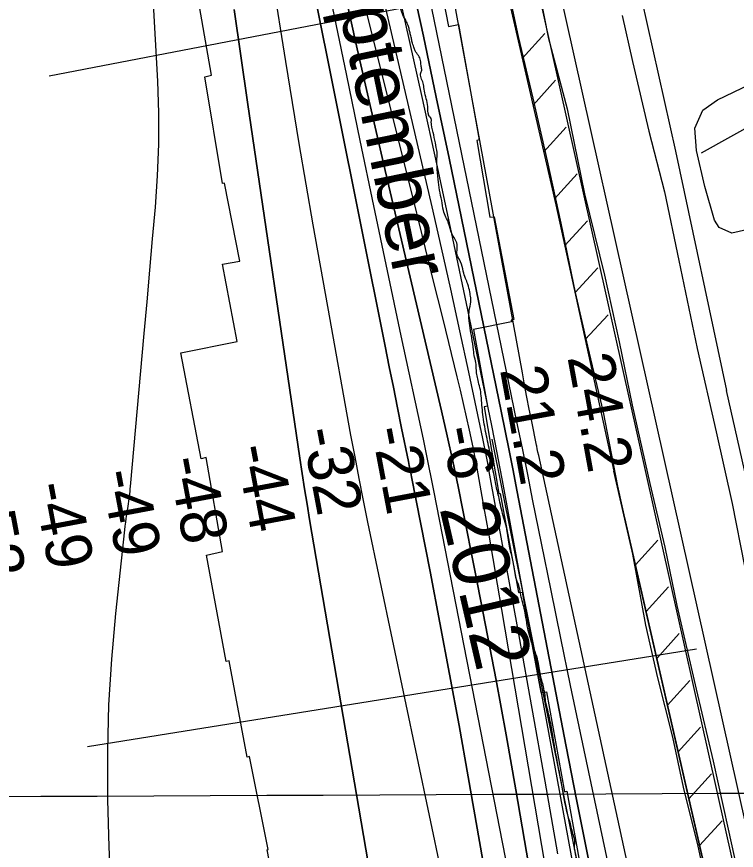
# Model space of a CAD drawing. Extents: x 3419139 to 3457078, y 540382 to 565875.
# Drawn here: x 3439284 to 3440334, y 551821 to 553037 of the extents above; entities that cross this region are included whole.
import ezdxf

# ---------------------------------------------------------------- set-up
doc = ezdxf.new("R2010")
doc.units = 0
for name, color, linetype in [('V-FLOD-BASE', 7, 'Continuous'), ('V-GRID-MAJR', 7, 'Continuous'), ('V-LEVE-TOET', 7, 'Continuous'), ('V-RIVR-EDGE', 7, 'Continuous'), ('V-RIVR-IDEN', 7, 'Continuous'), ('V-RIVR-RANG', 7, 'Continuous'), ('V-ROAD-CNTR', 7, 'Continuous'), ('V-RRAP-FSHR', 7, 'Continuous'), ('V-RRAP-RVMT', 7, 'Continuous'), ('V-SITE-VEGE', 7, 'Continuous'), ('V-SURV-LINE', 7, 'Continuous'), ('V-TOPO-DPTH', 7, 'Continuous'), ('V-TOPO-MAJR', 7, 'Continuous'), ('V-TOPO-MINR', 7, 'Continuous'), ('V-TOPO-SHOR', 7, 'Continuous'), ('V-TOPO-WATR', 7, 'Continuous')]:
    doc.layers.add(name, color=color, linetype=linetype)

msp = doc.modelspace()

# ---------------------------------------------------------------- linework, layer by layer
at = {"layer": 'V-FLOD-BASE'}
msp.add_lwpolyline([(3440043.2, 553091.6), (3440059.9, 553007.1), (3440087.4, 552902.3), (3440113, 552778.5), (3440141.9, 552659.9), (3440163.5, 552562.5), (3440182.4, 552470.3), (3440208, 552356), (3440229.9, 552263.3), (3440247.7, 552177.9), (3440275.5, 552056), (3440300.5, 551951), (3440322.5, 551851.8), (3440341.1, 551767.6), (3440361.6, 551677.7), (3440384.4, 551584.4), (3440400, 551514.2), (3440412.8, 551457.5), (3440426.1, 551391.2), (3440438.9, 551339), (3440453.6, 551276.9), (3440457.5, 551259.7)], dxfattribs=at)
at = {"layer": 'V-GRID-MAJR'}
msp.add_spline([(3423248.5, 551833.1), (3428523.1, 551854.2), (3433797.7, 551876), (3439072.3, 551898.7), (3444346.9, 551922.1), (3449621.5, 551946.2), (3454896.1, 551971.2)], degree=3, dxfattribs=at)
at = {"layer": 'V-LEVE-TOET'}
for points in [[(3440395.7, 551317.5), (3440385.5, 551375.7), (3440369.1, 551439.4), (3440351.4, 551520.9), (3440332.3, 551605.9), (3440306.4, 551696.4), (3440293.7, 551756.9), (3440278.7, 551827), (3440257.1, 551913.1), (3440241.8, 551985.9), (3440219.9, 552072.6), (3440202.4, 552149.6), (3440183.1, 552253.1), (3440161.2, 552352.3), (3440140.4, 552460.2), (3440117.7, 552556.3), (3440099.9, 552634.8), (3440078.9, 552735.7), (3440058.9, 552826.8), (3440037.8, 552918.2), (3440016.5, 553008.1), (3439996.8, 553101.5)], [(3440167.9, 553038.6), (3440182.9, 552971.3), (3440206.5, 552869.9), (3440229.5, 552781.3), (3440250.6, 552681), (3440277.4, 552552.9), (3440304.9, 552431.2), (3440328.2, 552326.7), (3440346.4, 552235.3), (3440367.8, 552133.6), (3440389.9, 552031), (3440415.2, 551920.6), (3440438.8, 551818.5), (3440464.3, 551705.3), (3440484.8, 551610.8), (3440506.1, 551517.8), (3440527.5, 551415.2), (3440545.7, 551326.4), (3440564.3, 551242.3), (3440575.7, 551189.9), (3440580.9, 551161.3)]]:
    msp.add_lwpolyline(points, dxfattribs=at)
at = {"layer": 'V-RIVR-EDGE'}
for points in [[(3439898, 552838.8), (3439895.2, 552852.9), (3439892, 552868.1), (3439889.3, 552883.9), (3439888.9, 552888.5), (3439886.8, 552891), (3439885.4, 552893.5), (3439884.7, 552896.3), (3439883.7, 552909), (3439881.2, 552919.9), (3439878.8, 552931.2), (3439877.4, 552940), (3439873.9, 552955.1), (3439875, 552957.6), (3439875, 552962.5), (3439874, 552969.2), (3439873.6, 552972.8), (3439870.5, 552980.2), (3439865.9, 552986.9), (3439863.8, 552992.5), (3439861.4, 552999.9), (3439860.3, 553005.6), (3439858.6, 553011.9), (3439857.2, 553017.9), (3439855.4, 553023.9), (3439852.3, 553031.3), (3439848.8, 553037.3), (3439845.6, 553045.1), (3439842.1, 553056.7), (3439838.3, 553071.2), (3439833.8, 553092.3), (3439828.9, 553114.2), (3439822.9, 553128.3), (3439821.9, 553133.9), (3439821.9, 553141.3), (3439820.5, 553150.5), (3439817, 553162.1), (3439816, 553169.9), (3439815.3, 553181.9), (3439812.9, 553202.3), (3439811.8, 553208.3), (3439810.4, 553213.6), (3439806.6, 553223.1), (3439803.4, 553233), (3439801, 553245.7), (3439798.2, 553251.3), (3439796.5, 553255.2), (3439794.4, 553261.6), (3439791.9, 553279.2), (3439786.7, 553298.2), (3439783.9, 553315.1), (3439782.9, 553320.1), (3439780.1, 553330), (3439779, 553338.4), (3439778, 553346.2), (3439774.5, 553358.9), (3439769.6, 553372.3), (3439764, 553387.8), (3439758.1, 553404.4), (3439752.8, 553419.5), (3439741.6, 553446.3), (3439736.7, 553454.1), (3439731.4, 553464.7), (3439730.4, 553470), (3439729.7, 553476.7), (3439729.7, 553486.5), (3439729, 553489), (3439726.9, 553492.2), (3439726.2, 553498.9), (3439724.9, 553513.7), (3439721.4, 553531.3), (3439717.5, 553552.8), (3439712.3, 553570.4), (3439710.2, 553579.6), (3439708.5, 553593.7), (3439705, 553614.2), (3439704.7, 553622.3), (3439704.7, 553626.5), (3439708.6, 553631.1), (3439711.1, 553635.3), (3439710.7, 553638.8), (3439709.3, 553643.7), (3439705.8, 553645.9), (3439697.7, 553653.6), (3439695.6, 553658.9), (3439695.3, 553664.9), (3439694.6, 553680.4), (3439696.7, 553685), (3439699.6, 553689.2), (3439699.2, 553692.8), (3439697.1, 553699.8), (3439696.1, 553710), (3439696.1, 553716.4), (3439695.4, 553735.8), (3439695.8, 553748.8), (3439695.2, 553762.5), (3439697.6, 553766.8), (3439697.7, 553771.3), (3439697, 553779.1), (3439694.9, 553788.3), (3439690.3, 553807.6), (3439684.4, 553823.5), (3439683.4, 553830.6), (3439684.8, 553836.2), (3439684.1, 553840.8), (3439681.6, 553846.8), (3439678.8, 553854.9), (3439676, 553862.3), (3439673.9, 553876.4), (3439675.4, 553881), (3439676.4, 553885.6), (3439676.5, 553890.8), (3439674, 553896.8), (3439671.5, 553900), (3439667.7, 553908.1), (3439664.2, 553925.8), (3439659.7, 553946.2), (3439656.9, 553950.1), (3439654.8, 553956.4), (3439651.7, 553979.7), (3439648.5, 553996.3), (3439644.7, 554015.7), (3439637.4, 554038.9), (3439632.8, 554059), (3439619.2, 554107.3), (3439614.7, 554128.1), (3439609.1, 554159.9), (3439602.5, 554201.1), (3439596.6, 554223.3), (3439592.8, 554245.2), (3439591, 554261.8), (3439592.8, 554281.8), (3439596.1, 554295.2), (3439598.2, 554308.6), (3439596.5, 554318.1), (3439590.5, 554329.4), (3439580.3, 554345.6), (3439576.5, 554348.5), (3439571.9, 554348.8), (3439568.4, 554349.6), (3439562.4, 554351.3), (3439561.3, 554354.9), (3439561, 554358), (3439561, 554363.3), (3439562.8, 554369.6), (3439563.8, 554378.5), (3439561.1, 554391.1), (3439558.3, 554406), (3439553.4, 554429.6), (3439551.7, 554441.9), (3439549.2, 554448.6), (3439546.8, 554453.6), (3439544.7, 554460.6), (3439544, 554469.8), (3439544, 554477.9), (3439543.9, 554480)], [(3440024.9, 552173.6), (3440019.4, 552196.1), (3440016.9, 552207.4), (3440012.7, 552218.7), (3440010.6, 552231), (3440007.8, 552246.2), (3440003.3, 552264.5), (3439999.5, 552289.2), (3439992.5, 552315.3), (3439989.4, 552329), (3439984.5, 552349.8), (3439980.3, 552370.6), (3439975.8, 552397.1), (3439969.9, 552424.9), (3439965, 552453.1), (3439962.3, 552480.6), (3439960.9, 552492.6), (3439958.1, 552503.9), (3439956, 552513.1), (3439955, 552521.5), (3439954.6, 552529.6), (3439952.5, 552540.2), (3439950.8, 552550.8), (3439948.4, 552568.4), (3439944.2, 552597), (3439944.6, 552607.9), (3439946.8, 552620.9), (3439946.8, 552626.9), (3439945.4, 552635.4), (3439942.6, 552646.7), (3439939.1, 552655.1), (3439935.9, 552665.7), (3439932.1, 552679.1), (3439927.2, 552689), (3439926.9, 552704.8), (3439919.2, 552720.4), (3439914.6, 552735.2), (3439906.9, 552754.2), (3439904.5, 552768.7), (3439901.3, 552783.8), (3439899.3, 552799.7), (3439897.6, 552818.7), (3439898, 552838.8)], [(3440142.2, 551559.1), (3440138.4, 551591.5), (3440135.6, 551613.4), (3440133.2, 551626.8), (3440131.4, 551638.4), (3440130.8, 551646.1), (3440130.1, 551651.4), (3440129, 551656), (3440126.9, 551665.2), (3440126.2, 551672.9), (3440124.5, 551681), (3440127, 551684.6), (3440127, 551686.7), (3440127, 551691.3), (3440125.6, 551700.8), (3440126, 551707.1), (3440125.6, 551711), (3440123.9, 551714.5), (3440120.4, 551717), (3440120.4, 551718.8), (3440119, 551728.3), (3440113.8, 551755.8), (3440107.1, 551779.4), (3440101.9, 551803.4), (3440099.1, 551819.6), (3440098.1, 551825.9), (3440098.8, 551835.1), (3440097.4, 551840.4), (3440092.2, 551859.4), (3440088, 551874.2), (3440079.3, 551918.7), (3440073, 551951.4), (3440067.1, 551985.6), (3440062.9, 552008.9), (3440057.7, 552031.1), (3440056, 552039.2), (3440055.6, 552043.8), (3440055.3, 552047.3), (3440054.2, 552052.6), (3440053.2, 552059.3), (3440050.4, 552068.8), (3440046.2, 552090.3), (3440043.1, 552103.7), (3440033.3, 552131.6), (3440030.1, 552144.7), (3440027.4, 552160.5), (3440024.9, 552173.6)]]:
    msp.add_spline(points, degree=3, dxfattribs=at)
at = {"layer": 'V-RIVR-RANG'}
for p, q in [((3440058.2, 553090.2), (3439331.6, 552949.9)), ((3440276.2, 552114.3), (3439387.5, 551972))]:
    msp.add_line(p, q, dxfattribs=at)
at = {"layer": 'V-ROAD-CNTR'}
for points in [[(3440179.2, 553136.9), (3440245.8, 552840.7), (3440319.8, 552491.5)], [(3440568.3, 551392.5), (3440319.8, 552491.5)]]:
    msp.add_lwpolyline(points, dxfattribs=at)
at = {"layer": 'V-RRAP-FSHR'}
for p, q in [((3440022.1, 552976.1), (3440054.8, 553012.3)), ((3440037.8, 552907.8), (3440070.5, 552944.1)), ((3440053.5, 552839.6), (3440086.2, 552875.9)), ((3440069.2, 552771.4), (3440101.9, 552807.7)), ((3440084.2, 552703), (3440117.3, 552738.9)), ((3440099.1, 552634.6), (3440132.2, 552670.5)), ((3440114, 552566.2), (3440147.1, 552602.1)), ((3440187.1, 552237.3), (3440219.8, 552273.5)), ((3440202.7, 552169.1), (3440235.4, 552205.3)), ((3440218.3, 552100.8), (3440251, 552137.1)), ((3440233.9, 552032.6), (3440266.7, 552068.8)), ((3440249.5, 551964.4), (3440282.3, 552000.6)), ((3440265.2, 551896.1), (3440297.9, 551932.4)), ((3440280.8, 551827.9), (3440313.5, 551864.1))]:
    msp.add_line(p, q, dxfattribs=at)
for points in [[(3439523, 556207.7), (3439541.4, 556021.5), (3439583, 555683.8), (3439624.1, 555273.4), (3439659.9, 554983.6), (3439685.1, 554824.7), (3439679.8, 554747.5), (3439685.3, 554704.8), (3439700.9, 554669.1), (3439728.3, 554557.2), (3439747.4, 554494.5), (3439772.6, 554275.3), (3439798, 554116.8), (3439825.3, 553912.3), (3439849.7, 553822.9), (3439865.1, 553645), (3439856.6, 553600.9), (3439862.4, 553565.7), (3439888.3, 553542.3), (3439924.4, 553445.5), (3439970.8, 553198.9), (3440071.2, 552762.5), (3440155.8, 552373.8)], [(3439960, 553256.3), (3439970.8, 553198.9), (3440071.2, 552762.5), (3440115.4, 552559.7)], [(3439977.8, 552420.6), (3440106.4, 551780.9), (3440172.3, 551404.3), (3440232, 551110), (3440392.8, 550607.1), (3440489.2, 549894.4), (3440511.6, 549607.3), (3440513.8, 549359.3), (3440532, 548929.5), (3440619.8, 548305.6), (3440691.1, 548058.6), (3440757.3, 547660.9), (3440767.5, 547537.4), (3440783.9, 547406), (3441072.2, 545849.7)], [(3440394.3, 551331.8), (3440155.8, 552373.8)], [(3440171.3, 552306.3), (3440316.6, 551671.5)]]:
    msp.add_lwpolyline(points, dxfattribs=at)
at = {"layer": 'V-RRAP-RVMT'}
for points in [[(3439610, 552680.4), (3439587.6, 552794), (3439584.5, 552793.5), (3439558.6, 552949.3), (3439568.5, 552951.5), (3439544.1, 553090.9), (3439541.7, 553090.4), (3439513.2, 553250.4), (3439533.4, 553254.4), (3439507.7, 553393.8), (3439816.4, 553456.1)], [(3439816.4, 553456.1), (3439874.9, 553165.7), (3439886.3, 553167.5), (3439914.5, 553022.7), (3439928.8, 553025.2), (3439959.1, 552857.3), (3439955.7, 552856.4), (3439974.6, 552744.4), (3439981.2, 552745.1), (3440009.9, 552595.1), (3440006, 552594.4)], [(3439584.8, 552256.8), (3439560.7, 552393.7), (3439553.6, 552392.2), (3439523.8, 552546.8), (3439606, 552563), (3439584.5, 552675.9), (3439610, 552680.4)], [(3440006, 552594.4), (3440006.5, 552591.6), (3439950.8, 552580.8), (3439971.2, 552468.6), (3439966.3, 552467.6), (3439987.6, 552341.4)], [(3439987.6, 552341.4), (3439989.8, 552341.6), (3440016.3, 552197), (3440021.9, 552197.4), (3440049.2, 552051), (3440057.3, 552052.2), (3440083.7, 551906.4), (3440086.9, 551907.1), (3440115.1, 551749.6), (3440112.3, 551748.7), (3440140.5, 551589.5), (3439869.6, 551535.5), (3439873.3, 551516.1), (3440144.3, 551568.9), (3440163.3, 551462.4), (3440157.4, 551460.8), (3440184.1, 551314.1), (3440181.7, 551313.8), (3440194.4, 551239.3), (3440204.9, 551240.9), (3440226.1, 551115.1)], [(3439850.8, 551161.3), (3439834.7, 551249.1), (3439754.6, 551233.1), (3439726.3, 551387.5), (3439740.1, 551390.5), (3439715.8, 551523.5), (3439709.5, 551522.7), (3439683.4, 551668.2), (3439679.3, 551667.6), (3439649.6, 551821.8), (3439651.4, 551822.2), (3439623.8, 551957.8), (3439620.7, 551957.1), (3439594.2, 552097.4), (3439590.1, 552096.3), (3439561.2, 552251.4), (3439584.8, 552256.8)]]:
    msp.add_lwpolyline(points, dxfattribs=at)
at = {"layer": 'V-SITE-VEGE'}
msp.add_lwpolyline([(3440359.8, 552728.5), (3440328, 552721.3), (3440309.5, 552729.4), (3440302.6, 552740.3), (3440288.2, 552789.1), (3440276.3, 552841.5), (3440273.9, 552874.1), (3440285.3, 552900.7), (3440307.1, 552915.6), (3440354.3, 552938.4)], dxfattribs=at)
at = {"layer": 'V-SURV-LINE'}
for points in [[(3440013.6, 553355.3), (3440576.5, 550835.5)], [(3440547.2, 550829), (3439984.3, 553348.8)]]:
    msp.add_lwpolyline(points, dxfattribs=at)
at = {"layer": 'V-TOPO-DPTH'}
for points in [[(3440074.1, 551815.8), (3440055.5, 551921.8), (3440036.6, 552027.7), (3440017.5, 552133.6), (3439973.9, 552373.5), (3439971.6, 552385.6), (3439969.3, 552397.6), (3439966.9, 552409.6), (3439964.4, 552421.5), (3439944, 552518.5), (3439931.1, 552578.9), (3439918, 552639.3), (3439904.4, 552699.5), (3439890.6, 552759.7), (3439772.1, 553268.5)], [(3440074.1, 551815.8), (3440055.5, 551921.8), (3440036.6, 552027.7), (3440017.5, 552133.6), (3439973.9, 552373.5), (3439971.6, 552385.6), (3439969.3, 552397.6), (3439966.9, 552409.6), (3439964.4, 552421.5), (3439944, 552518.5), (3439931.1, 552578.9), (3439918, 552639.3), (3439904.4, 552699.5), (3439890.6, 552759.7), (3439772.1, 553268.5)], [(3440073.2, 551137.8), (3440031.8, 551413.3), (3440026.8, 551445.6), (3440021.7, 551477.9), (3440016.3, 551510.2), (3440010.8, 551542.5), (3439943.1, 551928), (3439929.7, 552003), (3439916, 552077.9), (3439901.9, 552152.7), (3439887.5, 552227.5), (3439860.3, 552365.9), (3439859.2, 552371.4), (3439858.1, 552376.9), (3439857, 552382.4), (3439855.9, 552387.9), (3439846, 552436.6), (3439840, 552466.5), (3439833.9, 552496.4), (3439827.9, 552526.2), (3439821.9, 552556.1), (3439680.3, 553262.3)], [(3439680.3, 553262.3), (3439821.9, 552556.1), (3439827.9, 552526.2), (3439833.9, 552496.4), (3439840, 552466.5), (3439846, 552436.6), (3439855.9, 552387.9), (3439857, 552382.4), (3439858.1, 552376.9), (3439859.2, 552371.4), (3439860.3, 552365.9), (3439887.5, 552227.5), (3439901.9, 552152.7), (3439916, 552077.9), (3439929.7, 552003), (3439943.1, 551928), (3440010.8, 551542.5), (3440016.3, 551510.2), (3440021.7, 551477.9), (3440026.8, 551445.6), (3440031.8, 551413.3), (3440073.2, 551137.8)], [(3439858.6, 553097.4), (3439877.8, 553008.5), (3439896.6, 552919.4), (3439915.2, 552830.4), (3439991.4, 552461.5), (3439997.2, 552432.7), (3440003, 552403.9), (3440008.7, 552375), (3440014.3, 552346.2), (3440086.2, 551972.5), (3440101.3, 551894.9), (3440116.5, 551817.2), (3440132, 551739.6), (3440147.7, 551662.1), (3440164.4, 551580.1), (3440172, 551543.6), (3440179.7, 551507.1), (3440187.6, 551470.7), (3440195.6, 551434.2), (3440268.1, 551108.6)], [(3439922.4, 551700.7), (3439796.9, 552299.8), (3439790.4, 552331.4), (3439784.1, 552363.1), (3439778, 552394.8), (3439772.1, 552426.5), (3439738.1, 552614.2), (3439717, 552733.1), (3439696.5, 552852.1), (3439676.9, 552971.3), (3439657.9, 553090.5)], [(3439922.4, 551700.7), (3439796.9, 552299.8), (3439790.4, 552331.4), (3439784.1, 552363.1), (3439778, 552394.8), (3439772.1, 552426.5), (3439738.1, 552614.2), (3439717, 552733.1), (3439696.5, 552852.1), (3439676.9, 552971.3), (3439657.9, 553090.5)], [(3439761.6, 553078.6), (3439781.1, 552989.8), (3439801.3, 552901.1), (3439821.8, 552812.5), (3439904, 552462), (3439912.4, 552425.3), (3439920.6, 552388.5), (3439928.4, 552351.6), (3439935.9, 552314.7), (3439953, 552229.1), (3439968.6, 552149.2), (3439983.8, 552069.3), (3439998.3, 551989.3), (3440012.4, 551909.2), (3440072.6, 551559.5), (3440078.6, 551524.5), (3440084.7, 551489.6), (3440090.8, 551454.6), (3440096.9, 551419.7), (3440206.9, 550797.7)], [(3439761.6, 553078.6), (3439781.1, 552989.8), (3439801.3, 552901.1), (3439821.8, 552812.5), (3439904, 552462), (3439912.4, 552425.3), (3439920.6, 552388.5), (3439928.4, 552351.6), (3439935.9, 552314.7), (3439953, 552229.1), (3439968.6, 552149.2), (3439983.8, 552069.3), (3439998.3, 551989.3), (3440012.4, 551909.2), (3440072.6, 551559.5), (3440078.6, 551524.5), (3440084.7, 551489.6), (3440090.8, 551454.6), (3440096.9, 551419.7), (3440206.9, 550797.7)], [(3439601.7, 553047.3), (3439611.4, 552979.6), (3439621.3, 552912), (3439697.6, 552393.1), (3439701, 552370.7), (3439704.5, 552348.3), (3439708.1, 552325.9), (3439711.8, 552303.5), (3439852.8, 551478.7), (3439853.7, 551473.5), (3439854.6, 551468.4), (3439855.5, 551463.2), (3439856.4, 551458.1), (3439858.1, 551448.8), (3439858.2, 551448.3), (3439858.4, 551447.2), (3439859.2, 551442.9), (3439860.1, 551438), (3439861, 551433.2), (3439975.6, 550777.6)], [(3439975.6, 550777.6), (3439861, 551433.2), (3439860.1, 551438), (3439859.2, 551442.9), (3439858.4, 551447.2), (3439858.2, 551448.3), (3439858.1, 551448.8), (3439856.4, 551458.1), (3439855.5, 551463.2), (3439854.6, 551468.4), (3439853.7, 551473.5), (3439852.8, 551478.7), (3439711.8, 552303.5), (3439708.1, 552325.9), (3439704.5, 552348.3), (3439701, 552370.7), (3439697.6, 552393.1), (3439621.3, 552912), (3439611.4, 552979.6), (3439601.7, 553047.3)]]:
    msp.add_lwpolyline(points, dxfattribs=at)
at = {"layer": 'V-TOPO-MAJR'}
msp.add_lwpolyline([(3439483, 553064.8), (3439489.6, 552942.8), (3439491.1, 552896.8), (3439491.2, 552850.7), (3439489.5, 552804.7), (3439486.3, 552758.8), (3439482.2, 552712.8), (3439478.1, 552666.9), (3439474, 552620.9), (3439469.9, 552574.9), (3439449.9, 552351.6), (3439449.5, 552348), (3439449.2, 552344.4), (3439448.9, 552340.8), (3439448.5, 552337.2), (3439448.1, 552333.6), (3439447.7, 552330.1), (3439447.2, 552326.5), (3439446.7, 552322.9), (3439444.7, 552310.6), (3439443.8, 552305.1), (3439443, 552299.5), (3439442.3, 552294), (3439441.7, 552288.4), (3439428.6, 552166.5), (3439422.7, 552099.8), (3439418.5, 552033.2), (3439416.8, 551966.4), (3439416.8, 551899.5), (3439416.9, 551894.5), (3439418.8, 551826), (3439421.5, 551757.4)], dxfattribs=at)
at = {"layer": 'V-TOPO-MINR'}
for points in [[(3440369.5, 550876.9), (3440272.2, 551354.8), (3440266.6, 551382), (3440260.9, 551409.2), (3440255.1, 551436.3), (3440249.2, 551463.5), (3440240.7, 551502.5), (3440239, 551510.1), (3440237.4, 551517.7), (3440235.7, 551525.4), (3440234.1, 551533), (3440046, 552396.9), (3440044.9, 552401.7), (3440044.4, 552404.1), (3440043.9, 552406.5), (3440043.1, 552410.5), (3440042.8, 552411.7), (3440042.8, 552412.1), (3440035.8, 552446.6), (3440032.3, 552464.3), (3440028.9, 552482), (3440025.5, 552499.7), (3440022.2, 552517.4), (3439878, 553304.1)], [(3440133.9, 551596.3), (3439993.1, 552360.3), (3439989.4, 552380.5), (3439985.5, 552400.6), (3439981.5, 552420.7), (3439977.4, 552440.8), (3439942.5, 552609.3), (3439920.5, 552713.5), (3439898.3, 552817.7), (3439875.4, 552921.8), (3439852.2, 553025.7), (3439790.8, 553297.9)], [(3440041.1, 551586.5), (3439893.5, 552343.3), (3439889.7, 552362.7), (3439885.8, 552382), (3439881.8, 552401.4), (3439877.7, 552420.7), (3439845.5, 552571.6), (3439825.4, 552666.4), (3439805.4, 552761.2), (3439785.5, 552856.1), (3439765.8, 552950.9), (3439696.4, 553285.8)], [(3440073.2, 551137.8), (3440031.8, 551413.3), (3440026.8, 551445.6), (3440021.7, 551477.9), (3440016.3, 551510.2), (3440010.8, 551542.5), (3439943.1, 551928), (3439929.7, 552003), (3439916, 552077.9), (3439901.9, 552152.7), (3439887.5, 552227.5), (3439860.3, 552365.9), (3439859.2, 552371.4), (3439858.1, 552376.9), (3439857, 552382.4), (3439855.9, 552387.9), (3439846, 552436.6), (3439840, 552466.5), (3439833.9, 552496.4), (3439827.9, 552526.2), (3439821.9, 552556.1), (3439680.3, 553262.3)], [(3440292.2, 551126.9), (3440276, 551204.1), (3440259.4, 551281.3), (3440242.6, 551358.3), (3440218.3, 551468.6), (3440213.5, 551490.5), (3440208.7, 551512.5), (3440204, 551534.4), (3440199.3, 551556.3), (3440107.1, 551992.4), (3440092.6, 552061.5), (3440078.3, 552130.6), (3440064.1, 552199.8), (3440050.1, 552269), (3440037.6, 552330.9), (3440029.9, 552369.1), (3440022.1, 552407.4), (3440014.3, 552445.7), (3440006.4, 552483.9), (3439871.9, 553137.2)], [(3440099.1, 551541.1), (3439992.4, 552172.3), (3439986, 552209.4), (3439979.6, 552246.5), (3439973.1, 552283.5), (3439966.5, 552320.5), (3439954.6, 552386.8), (3439953.9, 552390.7), (3439953.2, 552394.6), (3439952.4, 552398.5), (3439951.6, 552402.3), (3439945, 552433.6), (3439940.8, 552453.1), (3439936.4, 552472.6), (3439931.9, 552492), (3439927.2, 552511.4), (3439906.4, 552595.6), (3439891.2, 552657.1), (3439875.9, 552718.6), (3439860.7, 552780), (3439845.4, 552841.5), (3439778.1, 553111.1)], [(3440268.1, 551108.6), (3440195.6, 551434.2), (3440187.6, 551470.7), (3440179.7, 551507.1), (3440172, 551543.6), (3440164.4, 551580.1), (3440147.7, 551662.1), (3440132, 551739.6), (3440116.5, 551817.2), (3440101.3, 551894.9), (3440086.2, 551972.5), (3440014.3, 552346.2), (3440008.7, 552375), (3440003, 552403.9), (3439997.2, 552432.7), (3439991.4, 552461.5), (3439915.2, 552830.4), (3439896.6, 552919.4), (3439877.8, 553008.5), (3439858.6, 553097.4)], [(3439922.4, 551700.7), (3439796.9, 552299.8), (3439790.4, 552331.4), (3439784.1, 552363.1), (3439778, 552394.8), (3439772.1, 552426.5), (3439738.1, 552614.2), (3439717, 552733.1), (3439696.5, 552852.1), (3439676.9, 552971.3), (3439657.9, 553090.5)], [(3440206.9, 550797.7), (3440096.9, 551419.7), (3440090.8, 551454.6), (3440084.7, 551489.6), (3440078.6, 551524.5), (3440072.6, 551559.5), (3440012.4, 551909.2), (3439998.3, 551989.3), (3439983.8, 552069.3), (3439968.6, 552149.2), (3439953, 552229.1), (3439935.9, 552314.7), (3439928.4, 552351.6), (3439920.6, 552388.5), (3439912.4, 552425.3), (3439904, 552462), (3439821.8, 552812.5), (3439801.3, 552901.1), (3439781.1, 552989.8), (3439761.6, 553078.6)], [(3439601.7, 553047.3), (3439611.4, 552979.6), (3439621.3, 552912), (3439697.6, 552393.1), (3439701, 552370.7), (3439704.5, 552348.3), (3439708.1, 552325.9), (3439711.8, 552303.5), (3439852.8, 551478.7), (3439853.7, 551473.5), (3439854.6, 551468.4), (3439855.5, 551463.2), (3439856.4, 551458.1), (3439858.1, 551448.8), (3439858.2, 551448.3), (3439858.4, 551447.2), (3439859.2, 551442.9), (3439860.1, 551438), (3439861, 551433.2), (3439975.6, 550777.6)]]:
    msp.add_lwpolyline(points, dxfattribs=at)
at = {"layer": 'V-TOPO-SHOR'}
msp.add_lwpolyline([(3440283.6, 552838.4), (3440847.8, 553153), (3441443.6, 553467.8), (3442075.7, 553760.1), (3443069, 554207.7)], dxfattribs=at)
at = {"layer": 'V-TOPO-WATR'}
msp.add_lwpolyline([(3440074.1, 551815.8), (3440055.5, 551921.8), (3440036.6, 552027.7), (3440017.5, 552133.6), (3439973.9, 552373.5), (3439971.6, 552385.6), (3439969.3, 552397.6), (3439966.9, 552409.6), (3439964.4, 552421.5), (3439944, 552518.5), (3439931.1, 552578.9), (3439918, 552639.3), (3439904.4, 552699.5), (3439890.6, 552759.7), (3439772.1, 553268.5)], dxfattribs=at)

# ---------------------------------------------------------------- texts
at = {"layer": 'V-RIVR-IDEN'}
for s, rotation, p in [('September', 281.6649, (3439727, 553181.6)), (' 2012', 283.0174, (3439894.1, 552350.1))]:
    msp.add_text(s, height=83, rotation=rotation, dxfattribs=at).set_placement(p)
at = {"layer": 'V-RIVR-RANG'}
for s, rotation, p in [('24.2', 280.4083, (3440087.7, 552540.4)), ('21.2', 280.4083, (3439989.3, 552522.1)), ('-32', 280.6887, (3439700.2, 552433.5)), ('-21', 280.6887, (3439801.7, 552435)), ('-6', 280.6887, (3439903.4, 552435.4)), ('-44', 280.6887, (3439603.1, 552408.7)), ('-48', 280.6887, (3439504.6, 552391.2)), ('-49', 280.6887, (3439406.5, 552372.1)), ('-49', 280.6887, (3439308.2, 552353.8)), ('-52', 280.6887, (3439208.9, 552340.4))]:
    msp.add_text(s, height=67, rotation=rotation, dxfattribs=at).set_placement(p)

doc.saveas('drawing.dxf')
